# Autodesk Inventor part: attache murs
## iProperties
Created: 2002-04
Part Number: attache murs
Material: Par défaut
Document SubType Name: Modélisation
Designer: Maison
Control State: 0
Master: False
Checked Out: False
Shininess: 27.0
Length Units: 11269
Angle Units: 11279
Time Units: 11290
Mass Units: 11283
Length Display Precision: 3
Angle Display Precision: 2
Density: 0.0
Volumn: 0.0
Area: 0.0
PropertySet Name: Model Information
Author: Maison
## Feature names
1. Extrusion2
2. Perçage1 [Hole]
3. Perçage2 [Hole]
